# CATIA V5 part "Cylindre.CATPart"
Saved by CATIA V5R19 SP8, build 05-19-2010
Part number: Cylindre
Revision: ANY
Definition: UNKNOWN
Nomenclature: 2
Source: Unknown
Bounding box of the stored display mesh (mm): x -18.5 to 16.5, y -10.998 to 10.978, z -11 to 0.691
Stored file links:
  D:\Documents\1_Travail\2- 2I2D\1 - Cours et TD\2- TD\3-TD Assemblage\Pompe AirMan\Cylindre.CATPart
  D:\Documents\1_Travail\3 -  Supports d'étude\Pompe_AirMan\Maquettes numériques_Pompe_AirMan\MaquettePompe_Catia\Clapet_refoulement.CATPart
  D:\Documents\1_Travail\3 -  Supports d'étude\Pompe_AirMan\Maquettes numériques_Pompe_AirMan\MaquettePompe_Catia\0-PompeAirman.CATProduct
  D:\Documents\1_Travail\3 -  Supports d'étude\Pompe_AirMan\Maquettes numériques_Pompe_AirMan\MaquettePompe_Catia\Piston.CATPart
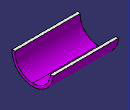
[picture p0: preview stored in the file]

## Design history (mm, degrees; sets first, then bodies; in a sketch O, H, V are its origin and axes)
AxisSystem1: origin (-7.2974, 0, 0), X (-1, 0, 0), Y (0, 1, 0), Z (0, 0, -1)
Set1
  Point1: stored without definition
Body1 "Révolution1" (main body)
  Solid1: solid without history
